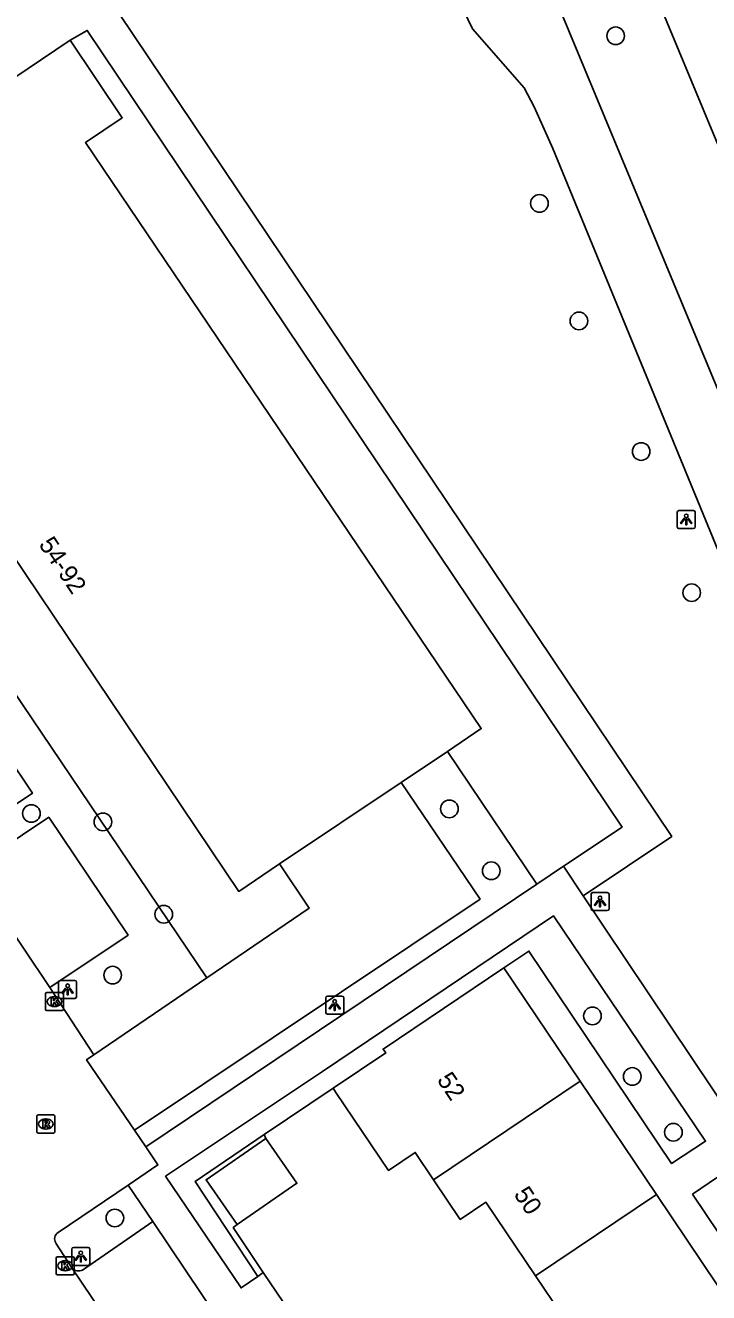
# Model space of a CAD drawing. Extents: x 158797 to 159887, y 384318 to 385255.
# Drawn here: x 159193.3 to 159231.2, y 384698.1 to 384768.4 of the extents above; entities that cross this region are included whole.
import ezdxf

# ---------------------------------------------------------------- set-up
doc = ezdxf.new("R2010")
doc.units = 0
for name, color, linetype in [('IMGEO_Boom', 7, 'Continuous'), ('IMGEO_Fietspad_gesloten', 7, 'Continuous'), ('IMGEO_Groenvoorziening', 7, 'Continuous'), ('IMGEO_Haag', 7, 'Continuous'), ('IMGEO_Kolk', 7, 'Continuous'), ('IMGEO_Lichtpunt', 7, 'Continuous'), ('IMGEO_Pand', 7, 'Continuous'), ('IMGEO_Pand_nummerreeks', 7, 'Continuous'), ('IMGEO_Parkeervlak_open', 7, 'Continuous'), ('IMGEO_Rijbaan_lokaal_gesloten', 7, 'Continuous'), ('IMGEO_Rijbaan_lokaal_open', 7, 'Continuous'), ('IMGEO_Rioolput', 7, 'Continuous'), ('IMGEO_Voetpad_open', 7, 'Continuous')]:
    doc.layers.add(name, color=color, linetype=linetype)

msp = doc.modelspace()

# ---------------------------------------------------------------- linework, layer by layer
at = {"layer": 'IMGEO_Boom'}
for centre in [(159226.076, 384767.789), (159221.85, 384758.492), (159224.041, 384751.97), (159227.491, 384744.728), (159230.293, 384736.897), (159193.673, 384724.648), (159216.854, 384724.904), (159197.64, 384724.182), (159219.179, 384721.47), (159201.014, 384719.057), (159198.18, 384715.681), (159224.791, 384713.419), (159226.998, 384710.06), (159229.278, 384706.965), (159198.302, 384702.21)]:
    msp.add_circle(centre, 0.489, dxfattribs=at)
at = {"layer": 'IMGEO_Fietspad_gesloten'}
msp.add_lwpolyline([(159261.072, 384690.903), (159252.164, 384712.413), (159242.416, 384735.94), (159233.011, 384758.687), (159224.228, 384779.872), (159221.922, 384785.43), (159221.439, 384786.574)], dxfattribs=at)
at = {"layer": 'IMGEO_Groenvoorziening'}
for points in [[(159176.436, 384755.504), (159203.402, 384715.53)], [(159210.407, 384709.411), (159206.574, 384706.837)], [(159206.574, 384706.837), (159202.764, 384704.24), (159206.227, 384698.971)], [(159206.677, 384706.627), (159206.574, 384706.837)], [(159206.536, 384699.187), (159204.867, 384701.674), (159205.089, 384701.841)]]:
    msp.add_lwpolyline(points, dxfattribs=at)
at = {"layer": 'IMGEO_Haag'}
msp.add_lwpolyline([(159216.746, 384728.092), (159221.701, 384720.727)], dxfattribs=at)
at = {"layer": 'IMGEO_Kolk'}
for p, q in [((159194.453, 384713.789), (159194.453, 384714.641)), ((159194.528, 384714.715), (159195.38, 384714.715)), ((159194.941, 384714.495), (159194.966, 384714.495)), ((159195.454, 384714.641), (159195.454, 384713.789)), ((159195.38, 384713.715), (159194.528, 384713.715)), ((159194.964, 384713.935), (159194.939, 384713.935)), ((159195.048, 384699.133), (159195.048, 384699.985)), ((159195.123, 384700.059), (159195.975, 384700.059)), ((159195.536, 384699.839), (159195.561, 384699.839)), ((159196.049, 384699.985), (159196.049, 384699.133)), ((159195.975, 384699.059), (159195.123, 384699.059)), ((159195.559, 384699.279), (159195.534, 384699.279))]:
    msp.add_line(p, q, dxfattribs=at)
for points in [[(159194.453, 384713.789), (159194.453, 384714.641)], [(159194.528, 384714.715), (159195.38, 384714.715)], [(159194.774, 384714.415), (159194.897, 384714.415), (159194.897, 384714.264), (159195.027, 384714.415), (159195.191, 384714.415), (159195.045, 384714.264), (159195.198, 384714.015), (159195.046, 384714.015), (159194.961, 384714.179), (159194.897, 384714.112), (159194.897, 384714.015), (159194.774, 384714.015), (159194.774, 384714.415)], [(159195.454, 384714.641), (159195.454, 384713.789)], [(159195.38, 384713.715), (159194.528, 384713.715)], [(159195.048, 384699.133), (159195.048, 384699.985)], [(159195.123, 384700.059), (159195.975, 384700.059)], [(159195.369, 384699.759), (159195.492, 384699.759), (159195.492, 384699.608), (159195.622, 384699.759), (159195.786, 384699.759), (159195.64, 384699.608), (159195.793, 384699.359), (159195.641, 384699.359), (159195.556, 384699.523), (159195.492, 384699.456), (159195.492, 384699.359), (159195.369, 384699.359), (159195.369, 384699.759)], [(159196.049, 384699.985), (159196.049, 384699.133)], [(159195.975, 384699.059), (159195.123, 384699.059)]]:
    msp.add_lwpolyline(points, dxfattribs=at)
for centre, start, end in [((159194.53, 384714.639), 91.55205, 178.44795), ((159194.53, 384714.639), 91.55205, 178.44795), ((159195.378, 384714.639), 1.55205, 88.44795), ((159195.378, 384714.639), 1.55205, 88.44795), ((159194.53, 384713.791), 181.55205, 268.44795), ((159194.53, 384713.791), 181.55205, 268.44795), ((159195.378, 384713.791), 271.55205, 358.44795), ((159195.378, 384713.791), 271.55205, 358.44795), ((159195.125, 384699.983), 91.55205, 178.44795), ((159195.125, 384699.983), 91.55205, 178.44795), ((159195.973, 384699.983), 1.55205, 88.44795), ((159195.973, 384699.983), 1.55205, 88.44795), ((159195.125, 384699.135), 181.55205, 268.44795), ((159195.125, 384699.135), 181.55205, 268.44795), ((159195.973, 384699.135), 271.55205, 358.44795), ((159195.973, 384699.135), 271.55205, 358.44795)]:
    msp.add_arc(centre, 0.0765, start, end, dxfattribs=at)
for centre, major_axis, ratio, start_param, end_param in [((159194.94, 384714.215), (-0.387, 0.002), 0.722429, 4.712389, 7.853982), ((159194.965, 384714.215), (-0.39, 0.002), 0.717154, 1.570796, 4.712389), ((159195.535, 384699.559), (-0.387, 0.002), 0.722429, 4.712389, 7.853982), ((159195.56, 384699.559), (-0.39, 0.002), 0.717154, 1.570796, 4.712389)]:
    msp.add_ellipse(centre, major_axis=major_axis, ratio=ratio, start_param=start_param, end_param=end_param, dxfattribs=at)
at = {"layer": 'IMGEO_Lichtpunt'}
for p, q in [((159229.493, 384741.358), (159229.493, 384740.551)), ((159229.493, 384741.358), (159229.493, 384740.551)), ((159230.395, 384741.453), (159229.587, 384741.453)), ((159230.395, 384741.453), (159229.587, 384741.453)), ((159230.489, 384740.551), (159230.489, 384741.358)), ((159230.489, 384740.551), (159230.489, 384741.358)), ((159229.587, 384740.457), (159230.395, 384740.457)), ((159229.587, 384740.457), (159230.395, 384740.457)), ((159224.712, 384720.168), (159224.712, 384719.361)), ((159224.712, 384720.168), (159224.712, 384719.361)), ((159225.614, 384720.263), (159224.806, 384720.263)), ((159225.614, 384720.263), (159224.806, 384720.263)), ((159225.708, 384719.361), (159225.708, 384720.168)), ((159225.708, 384719.361), (159225.708, 384720.168)), ((159224.806, 384719.267), (159225.614, 384719.267)), ((159224.806, 384719.267), (159225.614, 384719.267)), ((159195.183, 384715.294), (159195.183, 384714.487)), ((159195.183, 384715.294), (159195.183, 384714.487)), ((159196.085, 384715.389), (159195.277, 384715.389)), ((159196.085, 384715.389), (159195.277, 384715.389)), ((159196.179, 384714.487), (159196.179, 384715.294)), ((159196.179, 384714.487), (159196.179, 384715.294)), ((159195.277, 384714.393), (159196.085, 384714.393)), ((159195.277, 384714.393), (159196.085, 384714.393)), ((159209.997, 384714.424), (159209.997, 384713.617)), ((159209.997, 384714.424), (159209.997, 384713.617)), ((159210.899, 384714.519), (159210.091, 384714.519)), ((159210.899, 384714.519), (159210.091, 384714.519)), ((159210.993, 384713.617), (159210.993, 384714.424)), ((159210.993, 384713.617), (159210.993, 384714.424)), ((159210.091, 384713.523), (159210.899, 384713.523)), ((159210.091, 384713.523), (159210.899, 384713.523)), ((159195.913, 384700.48), (159195.913, 384699.673)), ((159195.913, 384700.48), (159195.913, 384699.673)), ((159196.815, 384700.575), (159196.007, 384700.575)), ((159196.815, 384700.575), (159196.007, 384700.575)), ((159196.909, 384699.673), (159196.909, 384700.48)), ((159196.909, 384699.673), (159196.909, 384700.48)), ((159196.007, 384699.579), (159196.815, 384699.579)), ((159196.007, 384699.579), (159196.815, 384699.579))]:
    msp.add_line(p, q, dxfattribs=at)
for points in [[(159229.867, 384741.022), (159229.906, 384740.994), (159229.718, 384740.732), (159229.68, 384740.759), (159229.867, 384741.022)], [(159229.969, 384740.974), (159230.016, 384740.974), (159230.016, 384740.652), (159229.969, 384740.652), (159229.969, 384740.974)], [(159230.079, 384740.994), (159230.117, 384741.021), (159230.304, 384740.759), (159230.265, 384740.731), (159230.079, 384740.994)], [(159225.086, 384719.832), (159225.125, 384719.804), (159224.937, 384719.542), (159224.899, 384719.569), (159225.086, 384719.832)], [(159225.188, 384719.784), (159225.235, 384719.784), (159225.235, 384719.462), (159225.188, 384719.462), (159225.188, 384719.784)], [(159225.298, 384719.804), (159225.336, 384719.831), (159225.523, 384719.569), (159225.484, 384719.541), (159225.298, 384719.804)], [(159195.557, 384714.958), (159195.596, 384714.93), (159195.408, 384714.668), (159195.37, 384714.695), (159195.557, 384714.958)], [(159195.659, 384714.91), (159195.706, 384714.91), (159195.706, 384714.588), (159195.659, 384714.588), (159195.659, 384714.91)], [(159195.769, 384714.93), (159195.807, 384714.957), (159195.994, 384714.695), (159195.955, 384714.667), (159195.769, 384714.93)], [(159210.371, 384714.088), (159210.41, 384714.06), (159210.222, 384713.798), (159210.184, 384713.825), (159210.371, 384714.088)], [(159210.473, 384714.04), (159210.52, 384714.04), (159210.52, 384713.718), (159210.473, 384713.718), (159210.473, 384714.04)], [(159210.583, 384714.06), (159210.621, 384714.087), (159210.808, 384713.825), (159210.769, 384713.797), (159210.583, 384714.06)], [(159196.287, 384700.144), (159196.326, 384700.116), (159196.138, 384699.854), (159196.1, 384699.881), (159196.287, 384700.144)], [(159196.389, 384700.096), (159196.436, 384700.096), (159196.436, 384699.774), (159196.389, 384699.774), (159196.389, 384700.096)], [(159196.499, 384700.116), (159196.537, 384700.143), (159196.724, 384699.881), (159196.685, 384699.853), (159196.499, 384700.116)]]:
    msp.add_lwpolyline(points, dxfattribs=at)
for centre in [(159229.992, 384741.156), (159225.211, 384719.966), (159195.682, 384715.092), (159210.496, 384714.222), (159196.412, 384700.278)]:
    msp.add_circle(centre, 0.0994, dxfattribs=at)
for centre, start, end in [((159229.587, 384741.358), 90, 180), ((159229.587, 384741.358), 90, 180), ((159230.395, 384741.358), 0, 90), ((159230.395, 384741.358), 0, 90), ((159229.587, 384740.551), 180, 270), ((159229.587, 384740.551), 180, 270), ((159230.395, 384740.551), 270, 0), ((159230.395, 384740.551), 270, 360), ((159224.806, 384720.168), 90, 180), ((159224.806, 384720.168), 90, 180), ((159225.614, 384720.168), 0, 90), ((159225.614, 384720.168), 0, 90), ((159224.806, 384719.361), 180, 270), ((159224.806, 384719.361), 180, 270), ((159225.614, 384719.361), 270, 0), ((159225.614, 384719.361), 270, 360), ((159195.277, 384715.294), 90, 180), ((159195.277, 384715.294), 90, 180), ((159196.085, 384715.294), 0, 90), ((159196.085, 384715.294), 0, 90), ((159195.277, 384714.487), 180, 270), ((159195.277, 384714.487), 180, 270), ((159196.085, 384714.487), 270, 0), ((159196.085, 384714.487), 270, 360), ((159210.091, 384714.424), 90, 180), ((159210.091, 384714.424), 90, 180), ((159210.899, 384714.424), 0, 90), ((159210.899, 384714.424), 0, 90), ((159210.091, 384713.617), 180, 270), ((159210.091, 384713.617), 180, 270), ((159210.899, 384713.617), 270, 0), ((159210.899, 384713.617), 270, 360), ((159196.007, 384700.48), 90, 180), ((159196.007, 384700.48), 90, 180), ((159196.815, 384700.48), 0, 90), ((159196.815, 384700.48), 0, 90), ((159196.007, 384699.673), 180, 270), ((159196.007, 384699.673), 180, 270), ((159196.815, 384699.673), 270, 0), ((159196.815, 384699.673), 270, 360)]:
    msp.add_arc(centre, 0.0946, start, end, dxfattribs=at)
at = {"layer": 'IMGEO_Pand'}
for points in [[(159184.841, 384754.512), (159187.029, 384755.979), (159184.556, 384759.741), (159188.06, 384762.115), (159187.97, 384762.253), (159195.817, 384767.542)], [(159195.817, 384767.542), (159198.715, 384763.242), (159196.667, 384761.862), (159218.626, 384729.354), (159216.746, 384728.092)], [(159207.44, 384721.848), (159205.176, 384720.329), (159183.02, 384753.29), (159184.841, 384754.512)], [(159216.746, 384728.092), (159214.184, 384726.373)], [(159207.44, 384721.848), (159214.184, 384726.373)], [(159210.407, 384709.411), (159213.322, 384711.368), (159213.181, 384711.578), (159219.882, 384716.093)], [(159219.882, 384716.093), (159224.111, 384709.799)], [(159215.977, 384704.335), (159214.96, 384705.849), (159213.476, 384704.85), (159210.565, 384709.176), (159210.407, 384709.411)], [(159224.111, 384709.799), (159215.977, 384704.335)], [(159224.111, 384709.799), (159228.339, 384703.504)], [(159205.089, 384701.841), (159203.364, 384704.333), (159206.677, 384706.627)], [(159205.089, 384701.841), (159208.403, 384704.135), (159206.677, 384706.627)], [(159215.977, 384704.335), (159217.46, 384702.129), (159218.881, 384703.083), (159221.632, 384698.999)], [(159221.632, 384698.999), (159228.339, 384703.504)], [(159228.339, 384703.504), (159232.568, 384697.21)], [(159221.632, 384698.999), (159224.471, 384694.783), (159223.043, 384693.829), (159224.442, 384691.752)]]:
    msp.add_lwpolyline(points, dxfattribs=at)
at = {"layer": 'IMGEO_Parkeervlak_open'}
for points in [[(159184.981, 384729.404), (159189.329, 384732.33), (159193.734, 384725.773), (159189.425, 384722.885)], [(159190.288, 384721.548), (159194.636, 384724.443), (159199.039, 384717.899), (159194.7, 384714.999)], [(159196.516, 384699.32), (159200.413, 384702.012)]]:
    msp.add_lwpolyline(points, dxfattribs=at)
msp.add_arc((159196.3, 384699.75), 0.481, 218.07599, 296.72369, dxfattribs=at)
at = {"layer": 'IMGEO_Rijbaan_lokaal_gesloten'}
for points in [[(159217.253, 384782.828), (159218.327, 384780.517), (159221.58, 384772.678), (159236.092, 384737.711), (159251.77, 384699.675), (159258.087, 384684.588), (159260.49, 384679.327)], [(159245.709, 384705.302), (159234.609, 384732.301), (159222.587, 384761.53), (159221.551, 384763.854), (159220.994, 384764.908), (159218.133, 384768.176), (159215.187, 384774.325)]]:
    msp.add_lwpolyline(points, dxfattribs=at)
at = {"layer": 'IMGEO_Rijbaan_lokaal_open'}
for points in [[(159214.184, 384726.373), (159218.554, 384719.899), (159199.393, 384707.074)], [(159194.7, 384714.999), (159190.288, 384721.548)], [(159203.402, 384715.53), (159209.073, 384719.388), (159207.44, 384721.848)], [(159197.133, 384711.265), (159203.402, 384715.53)], [(159194.7, 384714.999), (159197.133, 384711.265)], [(159199.393, 384707.074), (159196.731, 384710.991), (159197.133, 384711.265)], [(159200.012, 384706.16), (159199.393, 384707.074)], [(159200.012, 384706.16), (159200.688, 384705.155), (159199.041, 384704.037)], [(159195.154, 384701.397), (159199.041, 384704.037)], [(159195.921, 384699.453), (159195.02, 384700.822)], [(159203.61, 384688.038), (159195.921, 384699.453)]]:
    msp.add_lwpolyline(points, dxfattribs=at)
msp.add_arc((159195.387, 384701.04), 0.426, 123.07934, 210.68412, dxfattribs=at)
at = {"layer": 'IMGEO_Rioolput'}
for p, q in [((159193.975, 384706.998), (159193.975, 384707.85)), ((159194.05, 384707.924), (159194.902, 384707.924)), ((159194.463, 384707.704), (159194.488, 384707.704)), ((159194.976, 384707.85), (159194.976, 384706.998)), ((159194.902, 384706.924), (159194.05, 384706.924)), ((159194.486, 384707.144), (159194.461, 384707.144))]:
    msp.add_line(p, q, dxfattribs=at)
for points in [[(159193.975, 384706.998), (159193.975, 384707.85)], [(159194.05, 384707.924), (159194.902, 384707.924)], [(159194.564, 384707.622), (159194.312, 384707.624), (159194.312, 384707.224)], [(159194.312, 384707.224), (159194.436, 384707.224), (159194.436, 384707.386), (159194.447, 384707.386)], [(159194.49, 384707.543), (159194.436, 384707.543), (159194.436, 384707.462)], [(159194.436, 384707.462), (159194.488, 384707.462)], [(159194.494, 384707.357), (159194.565, 384707.224), (159194.705, 384707.224), (159194.64, 384707.35)], [(159194.976, 384707.85), (159194.976, 384706.998)], [(159194.902, 384706.924), (159194.05, 384706.924)]]:
    msp.add_lwpolyline(points, dxfattribs=at)
for centre, radius, start, end in [((159194.052, 384707.848), 0.0765, 91.55205, 178.44795), ((159194.052, 384707.848), 0.0765, 91.55205, 178.44795), ((159194.446, 384707.333), 0.0533, 26.02933, 88.69889), ((159194.472, 384707.651), 0.19, 274.7715, 282.96867), ((159194.496, 384707.447), 0.0964, 77.00612, 93.18647), ((159194.51, 384707.504), 0.0378, 276.66336, 79.67722), ((159194.563, 384707.512), 0.109, 350.36119, 89.41601), ((159194.561, 384707.512), 0.112, 277.58423, 350.98172), ((159194.545, 384707.297), 0.108, 29.51342, 73.79051), ((159194.9, 384707.848), 0.0765, 1.55205, 88.44795), ((159194.9, 384707.848), 0.0765, 1.55205, 88.44795), ((159194.052, 384707), 0.0765, 181.55205, 268.44795), ((159194.052, 384707), 0.0765, 181.55205, 268.44795), ((159194.9, 384707), 0.0765, 271.55205, 358.44795), ((159194.9, 384707), 0.0765, 271.55205, 358.44795)]:
    msp.add_arc(centre, radius, start, end, dxfattribs=at)
for centre, major_axis, ratio, start_param, end_param in [((159194.462, 384707.424), (-0.387, 0.002), 0.722429, 4.712389, 7.853982), ((159194.487, 384707.424), (-0.39, 0.002), 0.717154, 1.570796, 4.712389)]:
    msp.add_ellipse(centre, major_axis=major_axis, ratio=ratio, start_param=start_param, end_param=end_param, dxfattribs=at)
at = {"layer": 'IMGEO_Voetpad_open'}
for points in [[(159224.283, 384720.074), (159229.19, 384723.379), (159198.516, 384769.05), (159195.743, 384773.179)], [(159223.18, 384721.721), (159226.436, 384723.892), (159196.767, 384768.087), (159195.817, 384767.542)], [(159223.18, 384721.721), (159221.701, 384720.727)], [(159224.283, 384720.074), (159223.18, 384721.721)], [(159221.701, 384720.727), (159200.012, 384706.16)], [(159251.833, 384678.94), (159224.283, 384720.074)], [(159206.227, 384698.971), (159205.306, 384698.33), (159201.114, 384704.521), (159209.822, 384710.337), (159222.631, 384718.962), (159231.068, 384706.463), (159229.181, 384705.232), (159221.268, 384717.014), (159219.882, 384716.093)], [(159230.331, 384703.528), (159232.178, 384704.793), (159239.413, 384693.992), (159237.614, 384692.69), (159230.331, 384703.528)], [(159199.041, 384704.037), (159200.413, 384702.012)], [(159200.413, 384702.012), (159207.623, 384691.274)], [(159206.536, 384699.187), (159206.227, 384698.971)], [(159207.999, 384697.008), (159206.536, 384699.187)]]:
    msp.add_lwpolyline(points, dxfattribs=at)

# ---------------------------------------------------------------- texts
at = {"layer": 'IMGEO_Pand_nummerreeks'}
for s, rotation, p in [('54-92', 303.90743, (159194.047, 384739.573)), ('52', 303.9017, (159216.134, 384709.872)), ('50', 303.959, (159220.393, 384703.523))]:
    msp.add_text(s, height=1, rotation=rotation, dxfattribs=at).set_placement(p)

doc.saveas('drawing.dxf')
